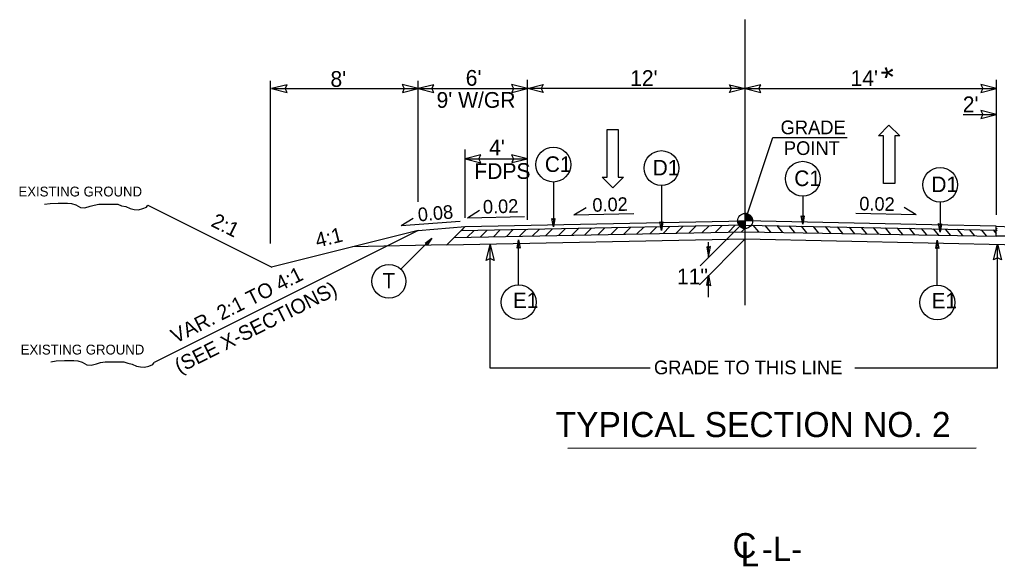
# Model space of a CAD drawing. Extents: x 573786 to 574032, y -53324 to -53148.
# Drawn here: x 573911.3 to 573965.4, y -53292 to -53261.7 of the extents above; entities that cross this region are included whole.
import ezdxf

# ---------------------------------------------------------------- set-up
doc = ezdxf.new("R2010")
doc.units = 0
for name, color, linetype in [('Default', 7, 'Continuous'), ('Prop Dimension', 7, 'Continuous'), ('Prop Dimension Text', 7, 'Continuous'), ('Prop Horizontal Alignment Curve and Spiral Data', 7, 'Continuous'), ('Prop Lane Arrow CELL', 7, 'Continuous'), ('Prop Shade Medium', 7, 'Continuous'), ('Typical Berm Information CELL', 7, 'Continuous'), ('Typical Curb CELL', 7, 'Continuous'), ('Typical Grade Point Symbol CELL', 7, 'Continuous'), ('Typical ID Circle CELL', 7, 'Continuous'), ('Typical Pavement Slope CELL', 7, 'Continuous'), ('Typical Pavement Slope Information CELL', 7, 'Continuous'), ('Typical Shoulder Slope CELL', 7, 'Continuous'), ('Typical Slope Point Local CELL', 7, 'Continuous'), ('Typical Terminator CELL', 7, 'Continuous'), ('Typical Text Centerline CELL', 7, 'Continuous'), ('Typical Text Grade Point CELL', 7, 'Continuous'), ('Typical Text ID Circle CELL', 7, 'Continuous'), ('Typical Text Label CELL', 7, 'Continuous')]:
    doc.layers.add(name, color=color, linetype=linetype)

# ---------------------------------------------------------------- blocks, each defined once
blk = doc.blocks.new('TERMINATOR')
at = {"layer": 'Typical Terminator CELL'}
blk.add_lwpolyline([(-0.469, 0.081), (0, 0), (-0.471, -0.083), (-0.411, 0)], close=True, dxfattribs=at)

msp = doc.modelspace()

# ---------------------------------------------------------------- linework, layer by layer
at = {"layer": 'Default'}
for points in [[(573912.727, -53271.942), (573913.03, -53271.899), (573913.484, -53271.877), (573913.786, -53271.877), (573914.002, -53271.877), (573914.218, -53271.899), (573914.456, -53271.964), (573914.715, -53272.115), (573914.953, -53272.137), (573915.255, -53272.05), (573915.471, -53271.985), (573915.731, -53271.942), (573916.033, -53271.942), (573916.271, -53271.942), (573916.508, -53271.942), (573916.768, -53271.942), (573916.984, -53272.029), (573917.221, -53272.072), (573917.459, -53272.18), (573917.675, -53272.223), (573917.913, -53272.245), (573918.15, -53272.18), (573918.367, -53272.093), (573918.431, -53271.985)], [(573913.072, -53280.643), (573913.375, -53280.599), (573913.828, -53280.578), (573914.131, -53280.578), (573914.347, -53280.578), (573914.563, -53280.599), (573914.801, -53280.664), (573915.06, -53280.815), (573915.298, -53280.837), (573915.6, -53280.751), (573915.816, -53280.686), (573916.075, -53280.643), (573916.378, -53280.643), (573916.615, -53280.643), (573916.853, -53280.643), (573917.112, -53280.643), (573917.328, -53280.729), (573917.566, -53280.772), (573917.804, -53280.88), (573918.02, -53280.924), (573918.258, -53280.945), (573918.495, -53280.88), (573918.711, -53280.794), (573918.776, -53280.686)]]:
    msp.add_lwpolyline(points, dxfattribs=at)
at = {"layer": 'Prop Dimension'}
for p, q in [((573936.084, -53273.765), (573936.462, -53273.387)), ((573936.806, -53273.75), (573937.183, -53273.372)), ((573937.527, -53273.736), (573937.905, -53273.358)), ((573938.249, -53273.721), (573938.627, -53273.343)), ((573938.97, -53273.707), (573939.348, -53273.329)), ((573939.692, -53273.692), (573940.07, -53273.314)), ((573940.413, -53273.678), (573940.791, -53273.3)), ((573941.135, -53273.663), (573941.513, -53273.285)), ((573941.856, -53273.649), (573942.234, -53273.271)), ((573942.578, -53273.634), (573942.956, -53273.256)), ((573943.3, -53273.62), (573943.678, -53273.242)), ((573944.021, -53273.605), (573944.399, -53273.228)), ((573944.743, -53273.591), (573945.121, -53273.213)), ((573945.464, -53273.577), (573945.842, -53273.199)), ((573946.186, -53273.562), (573946.564, -53273.184)), ((573946.907, -53273.548), (573947.285, -53273.17)), ((573947.629, -53273.533), (573948.007, -53273.155)), ((573948.351, -53273.519), (573948.729, -53273.141)), ((573949.072, -53273.504), (573949.45, -53273.126)), ((573949.794, -53273.49), (573950.172, -53273.112)), ((573950.515, -53273.475), (573950.893, -53273.097)), ((573951.237, -53273.461), (573951.438, -53273.26)), ((573951.438, -53273.357), (573951.438, -53273.086)), ((573951.871, -53273.095), (573952.186, -53273.47)), ((573952.535, -53273.109), (573952.848, -53273.482)), ((573953.199, -53273.122), (573953.511, -53273.494)), ((573953.863, -53273.135), (573954.174, -53273.506)), ((573954.527, -53273.149), (573954.837, -53273.518)), ((573955.19, -53273.162), (573955.499, -53273.53)), ((573955.854, -53273.175), (573956.162, -53273.542)), ((573956.518, -53273.189), (573956.825, -53273.554)), ((573957.182, -53273.202), (573957.487, -53273.566)), ((573957.846, -53273.215), (573958.15, -53273.578)), ((573958.51, -53273.229), (573958.813, -53273.59)), ((573959.174, -53273.242), (573959.476, -53273.602)), ((573959.838, -53273.255), (573960.138, -53273.614)), ((573960.502, -53273.269), (573960.801, -53273.625)), ((573961.165, -53273.282), (573961.464, -53273.637)), ((573961.829, -53273.295), (573962.126, -53273.649)), ((573962.493, -53273.309), (573962.789, -53273.661)), ((573963.157, -53273.322), (573963.452, -53273.673)), ((573963.821, -53273.335), (573964.115, -53273.685)), ((573964.485, -53273.349), (573964.777, -53273.697)), ((573965.149, -53273.362), (573965.319, -53273.565))]:
    msp.add_line(p, q, dxfattribs=at)
at = {"layer": 'Prop Dimension Text'}
for p, q in [((573925.203, -53274.108), (573925.203, -53265.118)), ((573933.366, -53271.803), (573933.365, -53265.117)), ((573939.406, -53272.794), (573939.406, -53265.066)), ((573965.335, -53272.528), (573965.335, -53265.065)), ((573925.272, -53265.55), (573933.365, -53265.55)), ((573933.365, -53265.55), (573939.406, -53265.55)), ((573951.437, -53265.549), (573939.406, -53265.55)), ((573951.437, -53265.549), (573965.319, -53265.549)), ((573963.482, -53266.983), (573965.335, -53266.983)), ((573935.967, -53272.698), (573935.967, -53268.913)), ((573935.967, -53269.425), (573939.406, -53269.425)), ((573937.349, -53280.99), (573937.349, -53274.183)), ((573965.381, -53280.988), (573965.381, -53274.146)), ((573946.186, -53280.989), (573937.349, -53280.99)), ((573965.381, -53280.988), (573957.502, -53280.989))]:
    msp.add_line(p, q, dxfattribs=at)
at = {"layer": 'Prop Lane Arrow CELL'}
for p, q in [((573958.804, -53268.168), (573959.385, -53267.577)), ((573959.385, -53267.577), (573959.985, -53268.168)), ((573943.813, -53270.439), (573943.813, -53267.814)), ((573943.813, -53267.814), (573944.432, -53267.814)), ((573944.432, -53267.814), (573944.432, -53270.439)), ((573959.085, -53268.168), (573958.804, -53268.168)), ((573959.085, -53270.793), (573959.085, -53268.168)), ((573959.985, -53268.168), (573959.704, -53268.168)), ((573959.704, -53268.168), (573959.704, -53270.793)), ((573944.132, -53271.029), (573943.532, -53270.439)), ((573943.532, -53270.439), (573943.813, -53270.439)), ((573944.713, -53270.439), (573944.132, -53271.029)), ((573944.432, -53270.439), (573944.713, -53270.439)), ((573959.704, -53270.793), (573959.085, -53270.793))]:
    msp.add_line(p, q, dxfattribs=at)
at = {"layer": 'Prop Shade Medium'}
for p, q in [((573935.967, -53273.174), (573951.438, -53272.864)), ((573961.751, -53273.07), (573951.438, -53272.864)), ((573961.751, -53273.07), (573951.438, -53272.864)), ((573951.438, -53272.864), (573951.438, -53273.086)), ((573951.438, -53273.086), (573935.74, -53273.401)), ((573935.74, -53273.401), (573935.967, -53273.174)), ((573951.438, -53273.086), (573961.751, -53273.292)), ((573951.438, -53273.086), (573961.751, -53273.292)), ((573965.319, -53273.143), (573961.751, -53273.07)), ((573965.319, -53273.143), (573961.751, -53273.07)), ((573961.751, -53273.292), (573965.319, -53273.365)), ((573961.751, -53273.292), (573965.319, -53273.365)), ((573965.319, -53273.365), (573965.319, -53273.143)), ((573965.319, -53273.365), (573965.319, -53273.143))]:
    msp.add_line(p, q, dxfattribs=at)
at = {"layer": 'Typical Curb CELL'}
for p, q in [((573965.319, -53273.708), (573965.319, -53273.143)), ((573965.319, -53273.143), (573967.014, -53273.214)), ((573967.739, -53273.708), (573965.319, -53273.708))]:
    msp.add_line(p, q, dxfattribs=at)
for centre in [(573965.335, -53273.381), (573965.352, -53273.288), (573965.33, -53273.68)]:
    msp.add_circle(centre, 0.00777, dxfattribs=at)
at = {"layer": 'Typical Grade Point Symbol CELL'}
for p, q in [((573951.438, -53272.864), (573952.975, -53268.251)), ((573951.438, -53272.864), (573951.438, -53272.449)), ((573951.022, -53272.864), (573951.438, -53272.864)), ((573951.437, -53273.28), (573951.438, -53272.864)), ((573951.438, -53272.864), (573951.437, -53273.28)), ((573951.853, -53272.864), (573951.438, -53272.864))]:
    msp.add_line(p, q, dxfattribs=at)
for points in [[(573951.441, -53272.449), (573951.441, -53272.449), (573951.441, -53272.864)], [(573951.45, -53272.449), (573951.45, -53272.864)], [(573951.458, -53272.45), (573951.458, -53272.864)], [(573951.466, -53272.45), (573951.466, -53272.864)], [(573951.475, -53272.45), (573951.475, -53272.864)], [(573951.483, -53272.451), (573951.483, -53272.864)], [(573951.491, -53272.452), (573951.491, -53272.864)], [(573951.5, -53272.453), (573951.5, -53272.864)], [(573951.508, -53272.454), (573951.508, -53272.864)], [(573951.516, -53272.456), (573951.516, -53272.864)], [(573951.525, -53272.458), (573951.525, -53272.864)], [(573951.533, -53272.46), (573951.533, -53272.864)], [(573951.541, -53272.462), (573951.541, -53272.864)], [(573951.549, -53272.464), (573951.549, -53272.864)], [(573951.558, -53272.466), (573951.558, -53272.864)], [(573951.566, -53272.469), (573951.566, -53272.864)], [(573951.574, -53272.472), (573951.574, -53272.864)], [(573951.583, -53272.474), (573951.583, -53272.864)], [(573951.591, -53272.478), (573951.591, -53272.864)], [(573951.599, -53272.482), (573951.599, -53272.864)], [(573951.608, -53272.486), (573951.608, -53272.864)], [(573951.616, -53272.489), (573951.616, -53272.864)], [(573951.624, -53272.493), (573951.624, -53272.864)], [(573951.633, -53272.498), (573951.633, -53272.864)], [(573951.641, -53272.502), (573951.641, -53272.864)], [(573951.649, -53272.507), (573951.649, -53272.864)], [(573951.024, -53272.864), (573951.024, -53272.909)], [(573951.032, -53272.864), (573951.032, -53272.958)], [(573951.041, -53272.864), (573951.041, -53272.988)], [(573951.049, -53272.864), (573951.049, -53273.013)], [(573951.057, -53272.864), (573951.057, -53273.032)], [(573951.066, -53272.864), (573951.066, -53273.05)], [(573951.074, -53272.864), (573951.074, -53273.066)], [(573951.082, -53272.864), (573951.082, -53273.08)], [(573951.091, -53272.864), (573951.091, -53273.093)], [(573951.099, -53272.864), (573951.099, -53273.105)], [(573951.107, -53272.864), (573951.107, -53273.116)], [(573951.115, -53272.864), (573951.115, -53273.126)], [(573951.124, -53272.864), (573951.124, -53273.137)], [(573951.132, -53272.864), (573951.132, -53273.146)], [(573951.14, -53272.864), (573951.14, -53273.155)], [(573951.149, -53272.864), (573951.149, -53273.163)], [(573951.157, -53272.864), (573951.157, -53273.171)], [(573951.165, -53272.864), (573951.165, -53273.178)], [(573951.174, -53272.864), (573951.174, -53273.186)], [(573951.182, -53272.864), (573951.182, -53273.192)], [(573951.19, -53272.864), (573951.19, -53273.199)], [(573951.199, -53272.864), (573951.199, -53273.204)], [(573951.207, -53272.864), (573951.207, -53273.21)], [(573951.215, -53272.864), (573951.215, -53273.215)], [(573951.223, -53272.864), (573951.224, -53273.221)], [(573951.232, -53272.864), (573951.232, -53273.225)], [(573951.24, -53272.864), (573951.24, -53273.23)], [(573951.248, -53272.864), (573951.248, -53273.235)], [(573951.257, -53272.864), (573951.257, -53273.238)], [(573951.265, -53272.864), (573951.265, -53273.242)], [(573951.273, -53272.864), (573951.273, -53273.246)], [(573951.282, -53272.864), (573951.282, -53273.249)], [(573951.29, -53272.864), (573951.29, -53273.253)], [(573951.298, -53272.864), (573951.298, -53273.256)], [(573951.307, -53272.864), (573951.307, -53273.259)], [(573951.315, -53272.864), (573951.315, -53273.261)], [(573951.323, -53272.864), (573951.323, -53273.263)], [(573951.332, -53272.864), (573951.332, -53273.266)], [(573951.34, -53272.864), (573951.34, -53273.268)], [(573951.348, -53272.864), (573951.348, -53273.27)], [(573951.357, -53272.864), (573951.357, -53273.271)], [(573951.365, -53272.864), (573951.365, -53273.273)], [(573951.373, -53272.864), (573951.373, -53273.274)], [(573951.381, -53272.864), (573951.381, -53273.276)], [(573951.39, -53272.864), (573951.39, -53273.277)], [(573951.398, -53272.864), (573951.398, -53273.278)], [(573951.406, -53272.864), (573951.406, -53273.279)], [(573951.415, -53272.864), (573951.415, -53273.279)], [(573951.423, -53272.864), (573951.423, -53273.28)], [(573951.431, -53272.864), (573951.431, -53273.28), (573951.431, -53273.28)], [(573951.658, -53272.511), (573951.658, -53272.864)], [(573951.666, -53272.517), (573951.666, -53272.864)], [(573951.674, -53272.522), (573951.674, -53272.864)], [(573951.682, -53272.529), (573951.682, -53272.864)], [(573951.691, -53272.534), (573951.691, -53272.864)], [(573951.699, -53272.541), (573951.699, -53272.864)], [(573951.707, -53272.548), (573951.707, -53272.864)], [(573951.716, -53272.556), (573951.716, -53272.864)], [(573951.724, -53272.563), (573951.724, -53272.864)], [(573951.732, -53272.571), (573951.732, -53272.864)], [(573951.741, -53272.58), (573951.741, -53272.864)], [(573951.749, -53272.589), (573951.749, -53272.864)], [(573951.757, -53272.599), (573951.757, -53272.864)], [(573951.766, -53272.609), (573951.766, -53272.864)], [(573951.774, -53272.62), (573951.774, -53272.864)], [(573951.782, -53272.632), (573951.782, -53272.864)], [(573951.791, -53272.645), (573951.791, -53272.864)], [(573951.799, -53272.659), (573951.799, -53272.864)], [(573951.807, -53272.674), (573951.807, -53272.864)], [(573951.815, -53272.691), (573951.815, -53272.864)], [(573951.824, -53272.711), (573951.824, -53272.864)], [(573951.832, -53272.734), (573951.832, -53272.864)], [(573951.84, -53272.763), (573951.84, -53272.864)], [(573951.849, -53272.805), (573951.849, -53272.864)]]:
    msp.add_lwpolyline(points, dxfattribs=at)
msp.add_circle((573951.437, -53272.864), 0.416, dxfattribs=at)
for start, end in [(359.9928, 89.9928), (179.9928, 269.9928)]:
    msp.add_arc((573951.437, -53272.864), 0.416, start, end, dxfattribs=at)
at = {"layer": 'Typical ID Circle CELL'}
for p, q in [((573940.841, -53270.709), (573940.841, -53273.194)), ((573946.816, -53270.901), (573946.816, -53273.387)), ((573954.624, -53271.491), (573954.624, -53273.044)), ((573962.216, -53271.825), (573962.216, -53273.483)), ((573948.954, -53275.347), (573951.438, -53272.864)), ((573932.419, -53275.535), (573934.133, -53273.821)), ((573938.924, -53276.387), (573938.924, -53273.902)), ((573948.919, -53276.386), (573951.448, -53273.858)), ((573949.423, -53274.878), (573949.423, -53274.029)), ((573962.06, -53276.406), (573962.06, -53273.921)), ((573949.423, -53277.081), (573949.423, -53275.954))]:
    msp.add_line(p, q, dxfattribs=at)
for centre, radius in [((573940.841, -53269.748), 0.962), ((573946.816, -53269.94), 0.962), ((573954.624, -53270.53), 0.962), ((573962.216, -53270.864), 0.962), ((573931.756, -53276.198), 0.938), ((573938.924, -53277.349), 0.962), ((573962.06, -53277.368), 0.962)]:
    msp.add_circle(centre, radius, dxfattribs=at)
at = {"layer": 'Typical Pavement Slope CELL'}
for p, q in [((573935.362, -53273.779), (573951.438, -53273.457)), ((573934.953, -53274.189), (573951.448, -53273.858))]:
    msp.add_line(p, q, dxfattribs=at)
at = {"layer": 'Typical Pavement Slope Information CELL'}
for p, q in [((573936.096, -53272.681), (573936.769, -53272.274)), ((573941.978, -53272.524), (573942.652, -53272.117)), ((573941.978, -53272.524), (573945.289, -53272.458)), ((573960.897, -53272.524), (573957.56, -53272.457)), ((573960.897, -53272.524), (573960.224, -53272.117)), ((573932.427, -53273.11), (573933.1, -53272.703)), ((573932.427, -53273.11), (573935.701, -53272.865)), ((573936.096, -53272.681), (573939.239, -53272.618))]:
    msp.add_line(p, q, dxfattribs=at)
at = {"layer": 'Typical Shoulder Slope CELL'}
msp.add_line((573933.366, -53273.391), (573935.967, -53273.174), dxfattribs=at)
at = {"layer": 'Typical Slope Point Local CELL'}
for p, q in [((573918.431, -53271.985), (573925.279, -53275.409)), ((573933.366, -53273.391), (573918.776, -53280.686)), ((573933.366, -53273.391), (573925.273, -53275.415)), ((573934.951, -53274.19), (573935.967, -53273.174)), ((573951.438, -53273.457), (573965.319, -53273.707)), ((573951.427, -53273.858), (573969.054, -53274.224)), ((573934.951, -53274.19), (573929.751, -53274.295))]:
    msp.add_line(p, q, dxfattribs=at)
at = {"layer": 'Typical Terminator CELL'}
for points in [[(573940.922, -53272.726), (573940.841, -53273.194), (573940.758, -53272.723), (573940.841, -53272.783)], [(573946.897, -53272.918), (573946.816, -53273.387), (573946.733, -53272.915), (573946.816, -53272.975)], [(573954.705, -53272.575), (573954.624, -53273.044), (573954.541, -53272.572), (573954.624, -53272.632)], [(573962.297, -53273.014), (573962.216, -53273.483), (573962.133, -53273.012), (573962.216, -53273.071)], [(573933.754, -53274.089), (573934.133, -53273.821), (573933.865, -53274.204), (573933.849, -53274.105)], [(573938.843, -53274.37), (573938.924, -53273.902), (573939.007, -53274.373), (573938.924, -53274.313)], [(573961.979, -53274.39), (573962.06, -53273.921), (573962.143, -53274.392), (573962.06, -53274.332)], [(573949.321, -53274.284), (573949.422, -53274.87), (573949.526, -53274.281), (573949.422, -53274.356)], [(573949.323, -53276.437), (573949.424, -53275.852), (573949.528, -53276.441), (573949.424, -53276.366)]]:
    msp.add_lwpolyline(points, close=True, dxfattribs=at)
at = {"layer": 'Typical Text Centerline CELL'}
for p, q in [((573951.437, -53263.632), (573951.437, -53261.735)), ((573951.438, -53268.081), (573951.437, -53263.632)), ((573951.438, -53277.507), (573951.438, -53268.081))]:
    msp.add_line(p, q, dxfattribs=at)
at = {"layer": 'Typical Text Grade Point CELL'}
msp.add_line((573952.975, -53268.251), (573957.081, -53268.251), dxfattribs=at)
at = {"layer": 'Typical Text Label CELL'}
msp.add_line((573941.633, -53285.408), (573964.212, -53285.407), dxfattribs=at)

# ---------------------------------------------------------------- block references
at = {"layer": 'Prop Dimension Text'}
for p, xscale, yscale, rotation in [((573925.272, -53265.55), 1.8461659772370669, -2.649824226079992, -179.99768562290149), ((573933.365, -53265.55), 1.8461659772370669, -2.649824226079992, 0.002314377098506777), ((573933.365, -53265.55), 1.8461659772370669, -2.649824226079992, -179.99768562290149), ((573939.406, -53265.55), 1.8461659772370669, -2.649824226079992, 0.002314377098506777), ((573939.406, -53265.55), 1.846165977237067, 2.6498242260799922, -179.99768562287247), ((573951.437, -53265.549), 1.846165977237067, 2.6498242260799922, 0.0023143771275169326), ((573951.437, -53265.549), 1.8461659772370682, -2.6498242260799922, -179.9976856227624), ((573965.335, -53265.549), 1.8461659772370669, -2.649824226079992, 0.002314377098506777), ((573965.335, -53266.983), 1.8461659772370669, -2.649824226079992, 0.002314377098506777), ((573935.967, -53269.425), 1.8461659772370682, -2.6498242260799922, -179.9976856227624), ((573939.406, -53269.425), 1.8461659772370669, -2.649824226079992, 0.002314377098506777), ((573937.349, -53274.183), 1.846165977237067, 2.6498242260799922, 90.0023143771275), ((573965.381, -53274.146), 1.846165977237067, 2.6498242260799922, 90.0023143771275)]:
    msp.add_blockref('TERMINATOR', p, dxfattribs=dict(at, xscale=xscale, yscale=yscale, rotation=rotation))

# ---------------------------------------------------------------- texts
for s, height, rotation, p in [('*', 1.28, 90, (573960.252, -53265.005)), ("8'", 0.8705, 0.0023, (573928.525, -53265.453)), ("6'", 0.8705, 0.0023, (573935.999, -53265.392)), ("12'", 0.8705, 0.0023, (573945.086, -53265.405)), ("14'", 0.8705, 0.0023, (573957.265, -53265.404)), ("9' W/GR", 0.8705, 0.0023, (573934.388, -53266.611)), ("2'", 0.8705, 0.0023, (573963.467, -53266.855)), ("4'", 0.8705, 0.0023, (573937.294, -53269.234)), ('FDPS', 0.8705, 0.0023, (573936.475, -53270.54)), ('11"', 0.8705, 0.0023, (573947.674, -53276.36))]:
    msp.add_text(s, height=height, rotation=rotation, dxfattribs=at).set_placement(p)
at = {"layer": 'Prop Horizontal Alignment Curve and Spiral Data'}
msp.add_text('-L-', height=1.3541, rotation=0.0023, dxfattribs=at).set_placement((573952.374, -53291.653))
at = {"layer": 'Typical Berm Information CELL'}
for s, rotation, p in [('0.02', 1.8107, (573936.964, -53272.461)), ('0.02', 1.8107, (573943.012, -53272.359)), ('0.08', 5.0828, (573933.387, -53272.893))]:
    msp.add_text(s, height=0.75, rotation=rotation, dxfattribs=at).set_placement(p)
at = {"layer": 'Typical Pavement Slope Information CELL'}
msp.add_text('0.02', height=0.75, rotation=358.8566, dxfattribs=at).set_placement((573957.743, -53272.273))
at = {"layer": 'Typical Slope Point Local CELL'}
for s, height, rotation, p in [('EXISTING GROUND', 0.54395, 0.0023, (573911.285, -53271.509)), ('2:1', 0.8124, 333.4373, (573921.866, -53273.123)), ('4:1', 0.8124, 14.0386, (573927.799, -53274.349)), ('VAR. 2:1 TO 4:1', 0.81244, 26.5645, (573919.965, -53279.647)), ('(SEE X-SECTIONS)', 0.81244, 26.5645, (573920.177, -53281.302)), ('EXISTING GROUND', 0.54395, 0.0023, (573911.407, -53280.242))]:
    msp.add_text(s, height=height, rotation=rotation, dxfattribs=at).set_placement(p)
at = {"layer": 'Typical Text Centerline CELL'}
for s, rotation, p in [('C', 0.0023, (573950.74, -53291.482)), ('L', 359.9492, (573951.196, -53291.95))]:
    msp.add_text(s, height=1.371, rotation=rotation, dxfattribs=at).set_placement(p)
at = {"layer": 'Typical Text Grade Point CELL'}
for s, height, p in [('GRADE', 0.7573, (573953.398, -53268.07)), ('POINT', 0.7573, (573953.58, -53269.217)), ('GRADE TO THIS LINE', 0.75728, (573946.401, -53281.334))]:
    msp.add_text(s, height=height, rotation=0.0023, dxfattribs=at).set_placement(p)
at = {"layer": 'Typical Text ID Circle CELL'}
for s, height, p in [('C1', 0.8608, (573940.372, -53270.154)), ('D1', 0.8608, (573946.335, -53270.346)), ('C1', 0.8608, (573954.155, -53270.936)), ('D1', 0.8608, (573961.735, -53271.27)), ('T ', 0.8393, (573931.407, -53276.584)), ('E1', 0.8608, (573938.604, -53277.678)), ('E1', 0.8608, (573961.74, -53277.697))]:
    msp.add_text(s, height=height, rotation=360, dxfattribs=at).set_placement(p)
at = {"layer": 'Typical Text Label CELL'}
msp.add_text(' TYPICAL SECTION NO. 2', height=1.38527, rotation=0.0023, dxfattribs=at).set_placement((573940.456, -53284.804))

doc.saveas('drawing.dxf')
